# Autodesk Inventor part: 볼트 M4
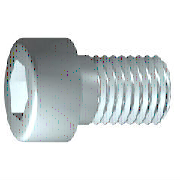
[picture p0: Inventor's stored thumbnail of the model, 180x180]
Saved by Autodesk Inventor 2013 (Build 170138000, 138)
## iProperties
IsCustomPart: 0
Created: 2015-12
Part Number: 볼트 M4
Material: 강철, 연강
Description: 6각머리 태핑 나사
Document SubType Name: Modeling
Standard: KS B 1003
Designer: mdu
Standards Organization: KS
Language: ko-KR
Size Designation: M 4 x 12
Categories: <MemberInstance><Categories><Category DisplayName="조임쇠" InternalName="e4da775c-781d-43d5-af7c-5136215cf5a6" Mnemonic="FSTN"><Category DisplayName="볼트" InternalN
Density: 1 g/cm^3
Author: mdu
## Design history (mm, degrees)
sketch "스케치1"
  geometry: L1 (-1, 0)-(12, 0); L2 (12, 0)-(12, 2); L3 (12, 2)-(1.75, 2); L4 (1.75, 2)-(1.32, 2); L5 (1.32, 2)-(0, 2); L6 (0, 2)-(0, 3.5); L7 (0, 3.5)-(-4, 3.5); L8 (-4, 3.5)-(-4, 1.732); L9 (-4, 1.732)-(-2, 1.732); L10 (-2, 1.732)-(-1, 0); L11 (-7.2, 0)-(15.2, 0) reference; L12 (0, -0.7)-(0, 4.2) reference; L13 (1.75, 2)-(0, 2)
  constraints: 22 end point, 6 parallel, 2 collinear, 2 perpendicular, 1 horizontal, 1 point on line
  dimensions: "d1" = 10.25 distance from line of L3.end L2 (= GEL); "d2" = 0.42952 distance of L4.end L3.end (computed from GAL); "d3" = 4 distance between parallel lines of L8 L6 (= KOH); "d4" = 2 distance of L8.end L9.end (= INTI); "d5" = 60 deg angle of L10 L1; "d6" = 4 diameter of L3 L1 (= GD); "d7" = 4 diameter of L5 L1 (= BDM); "d8" = 3.4641 diameter of L9 L1 (= 1.1547 x SW); "d9" = 7 diameter of L7 L1 (= KOD); "d26" = 12 distance between parallel lines of L12 L2 (= NLG)
revolve "본체" sketch "스케치1" stored, may be unused: angle "d10" = 90 deg
sketch "스케치2"
  geometry: L1 (0, -4.9)-(0, 4.9) reference; L2 (-4.9, 0)-(4.9, 0) reference; L3 (1.732, 0)-(0.866, -1.5); L4 (0.866, -1.5)-(-0.866, -1.5); L5 (-0.866, -1.5)-(-1.732, 0); L6 (-1.732, 0)-(-0.866, 1.5); L7 (-0.866, 1.5)-(0.866, 1.5); L8 (0.866, 1.5)-(1.732, 0); 2 further points
  constraints: 12 end point, 1 coincident, 1 horizontal alignment, 1 point on line, 12 other
extrude "슬롯" join sketch "스케치2" stored distance "d11" = 10; taper "d12" = 0 deg
workplane "Work Plane1"
fillet "Fillet2" dims "d30" = 0.1 (= R)
body "Solid1"
fillet "모깎기1" dims "d17" = 0.4 (= RR)
feature "스레드" dims "d13" = 10.25 (= GEL), "d14" = 0
chamfer "모따기1" distance "d15" = 0.42941 (= -0.5 x SPD + 0.5 x GD); stored, may be unused: second distance "d16" = 0.42941 (= GUL), angle "d27" = 45 deg
other parameters: "GD" = 4 (= NND) [user parameter; used in 2 equation terms], "NLG" = 12 [user parameter; used in 1 equation term], "GEL" = 10.25 [user parameter; used in 2 equation terms], "KOD" = 7 [user parameter; used in 1 equation term], "KOH" = 4 [user parameter; used in 1 equation term], "INTI" = 2 [user parameter; used in 1 equation term], "GAL" = 0.42941 (= 0.61345 x PTC) [user parameter; used in 1 equation term], "GUL" = 0.42941 (= 0.61345 x PTC) [user parameter; used in 1 equation term], "BDM" = 4 (= NND) [user parameter; used in 1 equation term], "SW" = 3 [user parameter; used in 2 equation terms], "RR" = 0.4 [user parameter; used in 1 equation term], "SPD" = 3.14117 (= NND - 1.2269 x PTC) [user parameter; used in 1 equation term], "d19" = 0, "d28" = 0, "d29" = 0, "R" = 0.1 [user parameter; used in 1 equation term], "PHH" = 0.2 [user parameter], "GD1" = 3.14117 (= THREADDIA - 1.2269 x PTC) [user parameter], "THREADDIA" = 4 [user parameter; used in 1 equation term], "FAWI" = 45 deg [user parameter], "TPU" = 14.28571 (computed from PTC) [user parameter], "PTC" = 0.7 [user parameter; used in 5 equation terms], "NND" = 4 [user parameter; used in 3 equation terms], "TOA" = 30 deg [user parameter], "E0" = 3.465 (= 1.155 x SW) [user parameter]
